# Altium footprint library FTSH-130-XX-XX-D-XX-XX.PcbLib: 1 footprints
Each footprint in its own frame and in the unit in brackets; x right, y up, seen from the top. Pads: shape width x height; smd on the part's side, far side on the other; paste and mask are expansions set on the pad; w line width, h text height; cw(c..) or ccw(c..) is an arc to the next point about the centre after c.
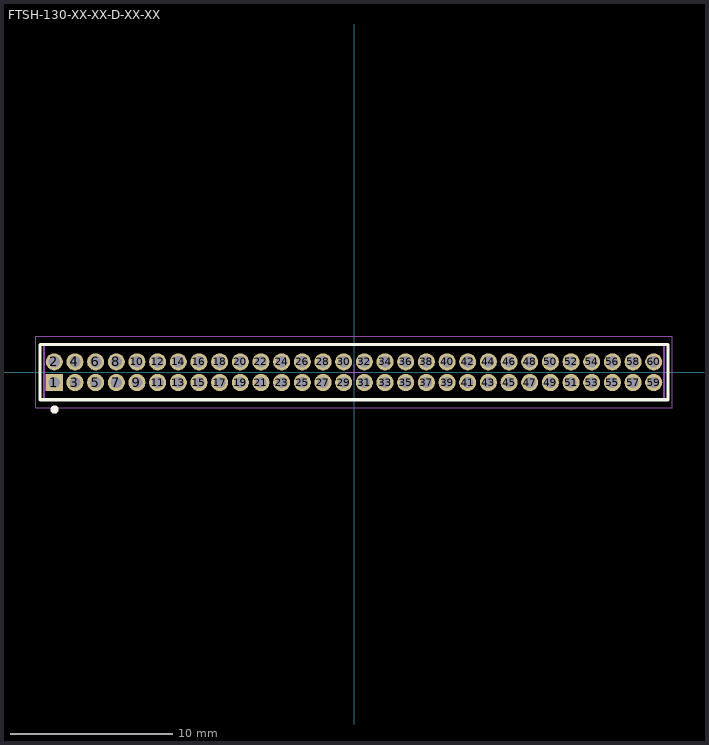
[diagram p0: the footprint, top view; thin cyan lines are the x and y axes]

## FTSH-130-XX-XX-D-XX-XX [mm] "1.27mm pitch, 60 pin, terminal strip; PTH"
height 3.05
pads (60):
  rect 1.05x1.05 / inner round 1.05 / far side rect 1.05x1.05 hole 0.7 unplated mask+0: 1(-18.415,-0.635)
  round 1.05 hole 0.7 unplated mask+0: 2(-18.415,0.635) 3(-17.145,-0.635) 4(-17.145,0.635) 5(-15.875,-0.635) 6(-15.875,0.635) 7(-14.605,-0.635) 8(-14.605,0.635) 9(-13.335,-0.635) 10(-13.335,0.635) 11(-12.065,-0.635) 12(-12.065,0.635) 13(-10.795,-0.635) 14(-10.795,0.635) 15(-9.525,-0.635) 16(-9.525,0.635) 17(-8.255,-0.635) 18(-8.255,0.635) 19(-6.985,-0.635) 20(-6.985,0.635) 21(-5.715,-0.635) 22(-5.715,0.635) 23(-4.445,-0.635) 24(-4.445,0.635) 25(-3.175,-0.635) 26(-3.175,0.635) 27(-1.905,-0.635) 28(-1.905,0.635) 29(-0.635,-0.635) 30(-0.635,0.635) 31(0.635,-0.635) 32(0.635,0.635) 33(1.905,-0.635) 34(1.905,0.635) 35(3.175,-0.635) 36(3.175,0.635) 37(4.445,-0.635) 38(4.445,0.635) 39(5.715,-0.635) 40(5.715,0.635) 41(6.985,-0.635) 42(6.985,0.635) 43(8.255,-0.635) 44(8.255,0.635) 45(9.525,-0.635) 46(9.525,0.635) 47(10.795,-0.635) 48(10.795,0.635) 49(12.065,-0.635) 50(12.065,0.635) 51(13.335,-0.635) 52(13.335,0.635) 53(14.605,-0.635) 54(14.605,0.635) 55(15.875,-0.635) 56(15.875,0.635) 57(17.145,-0.635) 58(17.145,0.635) 59(18.415,-0.635) 60(18.415,0.635)
Top Overlay:
  circle w0.25: c-18.4,-2.3 r0.125
  lines w0.2: -19.3,-1.7 19.3,-1.7 19.3,1.7 -19.3,1.7 -19.3,-1.7
Mechanical 12:
  lines w0.001: -19.05,-1.7 19.05,-1.7 19.05,1.7 -19.05,1.7 -19.05,-1.7
Mechanical 13:
  lines w0.1: -19.05,-1.7 19.05,-1.7 19.05,1.7 -19.05,1.7 -19.05,-1.7
  text ".Designator" at 0.254,0.381 h1.52
Mechanical 15:
  lines w0.05: -0.5,0 0.5,0 ; 0,-0.5 0,0.5 ; -19.55,-2.2 19.55,-2.2 19.55,2.2 -19.55,2.2 -19.55,-2.2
